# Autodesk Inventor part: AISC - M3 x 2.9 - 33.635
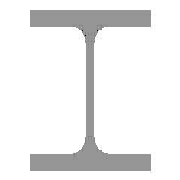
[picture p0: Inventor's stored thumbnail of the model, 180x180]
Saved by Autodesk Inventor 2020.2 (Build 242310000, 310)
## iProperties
_CCFamilyMember: 14
_CCFamilyDisplayName: ANSI M - M-Shape — Sizes in parentheses have been withdrawn
_FrameMemberDoc: Frame Member File
_Version: 15.0.0
_GetPNFromCC: 1
Created: 2020-01
Part Number: AISC - M3 x 2.9 - 33.635
Material: Steel, Mild
Description: M-Shape
Document SubType Name: Modeling
Standard: ANSI
Designer: thira
Standards Organization: ANSI
Language: en-US
Size Designation: M3 x 2.9
Categories: <MemberInstance><Categories><Category DisplayName="Structural Shapes" InternalName="089c4875-fa83-4c05-b084-43b9cc11f5ed" Mnemonic="GRDR"><CategoryParameter Dis
Stock Number: M3 x 2.9
Density: 7.85 g/cm^3
Appearance: Semi-Polished
G_L: 33.635 in
G_W: 2.250 in
G_H: 3.000 in
+2923C170-05DA-4238-8417-804BEE138335+CUTDETAIL1: Miter 45.00 deg
+2D74BDFD-F109-4072-BD78-AAB4B0D6E483+CUTDETAIL2: Miter 45.00 deg
IsCustomPart: 1
Author: thira
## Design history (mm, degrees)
node "Start Plane"
node "End Plane"
sketch "Sketch"
  geometry: L1 (-28.575, -38.1)-(-28.575, -34.798); L2 (-28.575, -34.798)-(-10.541, -34.798); L3 (-1.143, -25.4)-(-1.143, 0); L4 (-1.143, 0)-(0, 0); L5 (0, 0)-(0, -38.1); L6 (0, -38.1)-(-28.575, -38.1); L7 (-60, 0)-(80, 0); L8 (0, -60)-(0, 80); L9 (28.575, -38.1)-(28.575, -34.798); L10 (28.575, -34.798)-(10.541, -34.798); L11 (0, -38.1)-(28.575, -38.1); L12 (1.143, -25.4)-(1.143, 0); L13 (1.143, 0)-(0, 0); L14 (-28.575, 38.1)-(-28.575, 34.798); L15 (0, 38.1)-(-28.575, 38.1); L16 (0, 38.1)-(28.575, 38.1); L17 (28.575, 34.798)-(10.541, 34.798); L18 (-28.575, 34.798)-(-10.541, 34.798); L19 (1.143, 25.4)-(1.143, 0); L20 (-1.143, 25.4)-(-1.143, 0); L21 (28.575, 38.1)-(28.575, 34.798); L22 (0, 108)-(0, -88) reference; L23 (-88, 0)-(108, 0) reference; A1 r 9.398 centre (-10.541, 25.4) between (-1.143, 25.4) and (-10.541, 34.798); A2 r 9.398 centre (10.541, 25.4) between (10.541, 34.798) and (1.143, 25.4); A3 r 9.398 centre (10.541, -25.4) between (1.143, -25.4) and (10.541, -34.798); A4 r 9.398 centre (-10.541, -25.4) between (-10.541, -34.798) and (-1.143, -25.4); 4 further points
  constraints: 42 end point, 11 symmetric about line, 8 point on circle, 8 point on line, 8 tangent, 4 centre point, 4 collinear, 4 parallel, 3 equal radius, 1 perpendicular, 1 vertical, 13 other
  dimensions: "d1" = 38.1 vertical distance of L1.start L3.end (= 0.5 x G_H); "d2" = 3.302 distance between parallel lines of L2 L6 (= G_T1); "d3" = 28.575 distance from line of L5.end L1 (= 0.5 x G_W); "d4" = 1.143 distance between parallel lines of L5 L3 (= 0.5 x G_T); "d13" = 9.398 radius of A1 (= G_IR)
extrude "Body" new body sketch "Sketch" stored distance "d5" = 854.32157 (= G_L); taper "d6" = 0 deg
node "Driven Length"
  sketch "Sketch4"
    geometry: L1 (0, 0)-(10, 0) reference
    constraints: 2 end point, 1 horizontal
  workplane "Work Plane3"
  sketch "Sketch5"
    geometry: L1 (-2, -27.161)-(12, -27.161) reference; L2 (-2, 827.161)-(12, 827.161) reference
    dimensions: "d15" = 854.32157 distance between parallel lines of L1 L2 (derived)
workplane "Work Plane4"
split "Split1"
workplane "Work Plane5"
split "Split2"
body "Solid1"
other parameters: "G_W" = 57.15 [user parameter; used in 1 equation term], "G_H" = 76.2 [user parameter; used in 1 equation term], "G_T" = 2.286 [user parameter; used in 1 equation term], "G_T1" = 3.302 [user parameter; used in 1 equation term], "G_IR" = 9.398 [user parameter; used in 1 equation term], "G_L" = 854.32157 (= d15) [user parameter; used in 1 equation term], "G_OFFSET_START" = 27.16079 [user parameter; used in 1 equation term], "G_OFFSET_END" = 27.16079 [user parameter; used in 1 equation term], "d11" = -27.16079 (= -G_OFFSET_START), "d12" = 827.16079 (= G_OFFSET_END + B_L), "B_L" = 800 [user parameter; used in 1 equation term], "d14" = 90 deg
